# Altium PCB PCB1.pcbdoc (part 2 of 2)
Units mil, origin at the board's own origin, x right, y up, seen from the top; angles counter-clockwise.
Board outline 5175 x 2060 mil, 4 copper layers (Top Layer, Inner1, Inner2, Bottom Layer), stack 62.447 mil thick; 102 components, 59 nets, 316 pads, 177 vias.
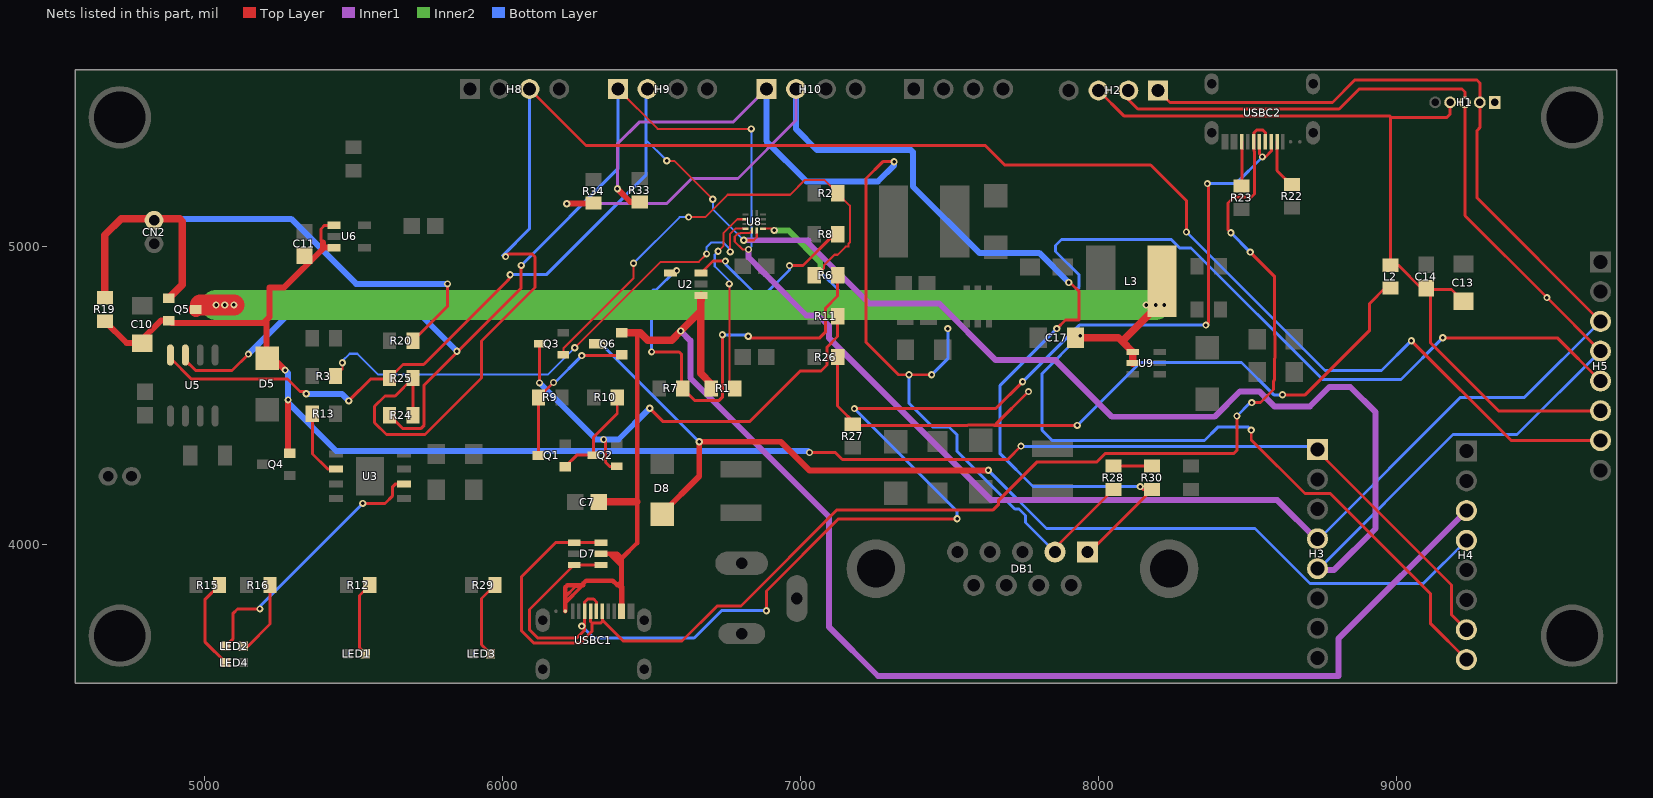
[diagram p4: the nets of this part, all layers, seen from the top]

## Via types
v1: diameter 24.02, hole 12, Top Layer to Bottom Layer, 177 vias

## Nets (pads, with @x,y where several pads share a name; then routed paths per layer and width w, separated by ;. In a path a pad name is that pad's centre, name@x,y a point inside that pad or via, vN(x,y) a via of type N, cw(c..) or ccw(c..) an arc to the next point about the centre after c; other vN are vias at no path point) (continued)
ID_INV: Q2.1 Q3.3 R11.2 | length 1618
  Top Layer w10: v1(6123.78,4543.56) 6123.78,4674.06 Q3.3@6124.73,4675 ; v1(6338.78,4353.57) 6345,4347.35 6345,4277.35 6358.78,4263.57 Q2.1@6383.47,4263.57 ; v1(6493.78,4458.57) 6538.78,4413.57 6828.78,4413.57 6998.78,4583.56 7068.78,4583.56 7088.78,4603.56 7088.78,4663.56 7124.37,4699.16 R11.2@7124.37,4767.5
  Bottom Layer w20: v1(6123.78,4543.56) 6313.78,4353.57 v1(6338.78,4353.57) 6388.78,4353.57 v1(6493.78,4458.57)
LED_CHG_A: LED4.1 R15.2 | length 309.2
  Top Layer w10: R15.2@5049.37,3865 5000.47,3816.1 5000.47,3675 LED4.1@5070.47,3605
LED_DONE_A: LED2.2 R16.2 | length 251.3
  Top Layer w10: LED2.2@5129.49,3660.01 5145,3660 5219.37,3734.37 R16.2@5219.37,3865
LED_EXT_A: LED1.2 R12.2 | length 252.7
  Top Layer w10: LED1.2@5539.56,3635 5519.56,3655 5519.56,3830.2 R12.2@5554.37,3865
LED_ON_A: LED3.2 R29.2 | length 261
  Top Layer w10: LED3.2@5959.49,3635.01 5929.49,3665 5929.49,3820.12 R29.2@5974.37,3865
PROG: R13.1 U3.2 | length 234.9
  Top Layer w10: R13.1@5360.63,4440 5361.88,4438.75 5361.88,4305 5411.88,4255 U3.2@5440.5,4255
PWR_SW_G: CN2.2 Q5.1 R19.2 R20.1 | length 2088.3
  Top Layer w10: R20.1@5699.37,4685 5815,4800.63 v1(5815,4876.01)
  Top Layer w25: R19.2@4665,4829.37 4665,5040 4720,5095 4829.37,5095 4830,5094.37 4915.63,5094.37 4925,5085 4925,4872.68 Q5.1@4879.73,4827.4
  Bottom Layer w20: CN2.2@4830,5094.37 5290,5094.37 5508.36,4876.01 v1(5815,4876.01)
Q2_G: Q1.1 Q2.3 R10.2 | length 337.7
  Top Layer w10: Q1.1@6210.27,4262.6 6248.65,4300.97 Q2.3@6304.73,4300.97 6304.72,4360.97 6384.72,4440.97 6384.72,4494.64 R10.2@6384.37,4495
RS485_A: DB1.1 H10.2 R30.1 R34.1 | length 4004.9
  Top Layer w10: v1(7860,4725.63) 7889.37,4755 7935,4755 7935,4850 7904.37,4880.63 v1(7900,4880.63) ; DB1.1@7963.11,3975.9 7970.28,3975.9 R30.1@8180,4185.63 8150,4185.63 v1(8140,4195.63)
  Top Layer w20: v1(6215,5145) 6302.66,5145 R34.1@6305.39,5147.73
  Inner1 w10: v1(6215,5145) 6550,5145 6635,5230 6790,5230 6985,5425 H10.2@6985,5530
  Bottom Layer w10: v1(7860,4725.63) 7670,4535.63 7670,4305.63 7780,4195.63 v1(8140,4195.63)
  Bottom Layer w20: H10.2@6985,5530 6985,5395 7055,5325 7370,5325 7377.07,5317.93 7377.07,5202.93 7600,4980 7800.63,4980 v1(7900,4880.63)
RS485_B: DB1.2 H10.1 R28.2 R33.1 | length 3753.1
  Top Layer w10: v1(7314.06,5285.9) 7275.9,5285.9 7220,5230 7220,4680 7329.1,4570.9 v1(7364.06,4570.9) v1(7440,4570.9) ; DB1.2@7854.05,3975.9 7854.06,3989.68 R28.2@8050,4185.63
  Top Layer w20: v1(6385,5195) 6429.37,5150.63 R33.1@6460,5150.63
  Inner1 w10: v1(6385,5195) 6385,5345 6460,5420 6775,5420 H10.1@6885,5530
  Bottom Layer w10: v1(7364.06,4570.9) 7364.06,4475.17 7443.39,4395.84 7497.99,4395.84 7525.54,4368.29 7525.54,4313.69 7719.24,4120 7733.38,4120 7755,4098.37 7755,4074.96 DB1.2@7854.05,3975.9 ; v1(7440,4570.9) 7494.06,4624.96 v1(7494.06,4725.9)
  Bottom Layer w20: H10.1@6885,5530 6885,5355 7020,5220 7260,5220 7314.06,5274.06 v1(7314.06,5285.9)
SCL: H1.3 H2.2 H3.5 H5.4 H9.2 R25.1 U5.4 U8.8 | length 9488.2
  Top Layer w7.09: v1(6550.63,5288.99) 6576.64,5288.99 v1(6705.45,5160.18) ; v1(6809.48,5022.35) 6842.98,5022.35 6852.87,5032.24 U8.8@6852.87,5055.47
  Top Layer w10: U5.4@4885,4637.37 4885,4626.93 4955,4556.93 5278.07,4556.93 5320,4515 5333,4515 v1(5341.07,4506.93) ; v1(5483.72,4483.35) 5557.29,4556.93 5617.56,4556.93 R25.1@5620.63,4560 5665.63,4605 5735,4605 6017,4887 6017,4887.73 6025.16,4895.89 v1(6025.16,4906.64) ; H2.2@8100,5525 8100,5495 8132,5463 8808,5463 8875,5530 9220,5530 9230,5520 H1.3@9230,5485 9230,5105 v1(9505,4830) H5.4@9685,4650
  Inner1 w20: v1(6809.48,5022.35) 7024.79,5022.35 7026.07,5021.07 ; 7020,5020 7230,4810 7465,4810 7655,4620 7855,4620 8045,4430 8390,4430 8475,4515 8540,4515 8590,4465 8710,4465 8775,4530 8845,4530 8930,4445 8930,4055 8790,3915 H3.5@8735,3915
  Bottom Layer w7.09: 6480.63,5360 6550.63,5290 v1(6550.63,5288.99) ; v1(6705.45,5160.18) 6705.45,5126.38 v1(6809.48,5022.35)
  Bottom Layer w10: v1(6025.16,4906.64) 6146.64,4906.64 6480.63,5240.63 6480.63,5360 6480.63,5523.96 H9.2@6486.67,5530 ; H3.5@8735,3915 9190,4370 9405,4370 H5.4@9685,4650
  Bottom Layer w20: v1(5341.07,4506.93) 5460.14,4506.93 v1(5483.72,4483.35)
SDA: H1.2 H2.1 H3.4 H5.3 H9.1 R24.1 U5.3 U8.7 | length 9385.5
  Top Layer w7.09: H9.1@6386.67,5530 6520.66,5396.01 v1(6834.73,5396.01) ; v1(6825.24,4991.39) 6805.46,4991.39 6779.25,5017.6 6779.25,5034.25 6790,5045 6797.41,5045 6799.31,5046.9 6829.78,5046.9 6835.96,5053.08 6835.96,5054.3 U8.7@6837.13,5055.47
  Top Layer w10: U5.3@4935,4637.37 4935,4620 4970,4585 5091.67,4585 v1(5146.67,4640) ; R24.1@5620.63,4435 5665.63,4390 5725,4390 5736.67,4401.67 5736.67,4536.67 6062.37,4862.37 v1(6062.37,4937.74) ; H2.1@8200,5525 8240,5485 8785,5485 8860,5560 9270,5560 9280,5550 H1.2@9280,5485 9280,5400 9270,5390 9270,5165 H5.3@9685,4750
  Inner1 w20: v1(6825.24,4991.39) 6825.24,4964.76 6878.17,4911.83 6878.58,4911.83 6882.99,4907.42 6883.17,4907.42 6900.74,4889.84 6900.74,4889.26 7020,4770 7060,4770 7095,4735 7095,4695 7640,4150 8600,4150 H3.4@8735,4015
  Bottom Layer w7.09: v1(6825.24,4991.39) 6834.73,5000.88 v1(6834.73,5396.01)
  Bottom Layer w10: v1(6062.37,4937.74) 6386.67,5262.03 H9.1@6386.67,5530 ; H3.4@8740.63,4015 8735,4015 9215,4495 9430,4495 H5.3@9685,4750
  Bottom Layer w20: v1(5146.67,4640) 5281.67,4775 5721.67,4775 v1(5846.67,4650)
SENS_PWR: C13.1 C14.2 H1.4 H2.3 H5.6 L2.2 | length 2871.9
  Top Layer w10: H2.3@8000,5525 8085,5440 8976.66,5440 8981.66,5435 ; C14.2@9100,4860.63 9084.37,4860.63 9006.96,4938.04 L2.2@8980,4938.04 8980,5433.34 8981.66,5435 ; H1.4@9180,5475 9180,5445 9170,5435 8981.66,5435 ; C13.1@9225,4817.3 9185,4857.3 9115,4857.3 9115,4677.3 9342.3,4450 H5.6@9685,4450
SENS_SEL: L2.1 R26.2 R27.2 | length 2536
  Top Layer w10: R26.2@7124.37,4630 7124.37,4465.72 7188.88,4401.21 7560.83,4401.21 cw(c7565.63,4390.21) 7565.63,4402.21 7644.37,4402.21 cw(c7644.37,4390.21) 7649.17,4401.21 7928.28,4401.21 v1(7928.64,4400.84) ; 7655,4404.37 v1(7765,4514.37) ; v1(8617.54,4503.71) 8693.71,4503.71 8910,4720 8910,4810 8961.96,4861.96 L2.1@8980,4861.96
  Bottom Layer w10: v1(7928.64,4400.84) 8139.76,4611.96 8480,4611.96 8588.26,4503.71 v1(8617.54,4503.71)
SINK_G: Q1.3 Q6.1 R9.1 | length 534.1
  Top Layer w10: Q1.3@6119.73,4300 6119.73,4494.09 R9.1@6120.63,4495 v1(6170.63,4545) ; v1(6265.63,4635) 6397.67,4635 Q6.1@6400.27,4637.6
  Bottom Layer w10: v1(6170.63,4545) 6175.63,4545 v1(6265.63,4635)
SRC_EN_N: R6.2 R7.2 U2.4 | length 1461
  Top Layer w10: v1(6500,4647.49) 6592.51,4647.49 6600,4640 6600,4529.37 R7.2@6604.37,4525 6644.37,4485 6727.21,4485 6737.44,4495.23 v1(6737.44,4705) ; v1(6824.37,4700) 6829.37,4695 7054.06,4694.94 ; 7054.13,4695 7064.37,4695 7084.37,4715 7084.37,4795 7124.37,4835 R6.2@7124.37,4905
  Bottom Layer w10: v1(6500,4647.49) 6500,4850.08 6504.92,4855 6515,4855 v1@6580,4920 ; v1(6737.44,4705) 6819.37,4705 v1(6824.37,4700)
  other v1: 6583.9,4920.27
STDBY_N: LED2.1 U3.6 | length 897.7
  Top Layer w10: LED2.1@5070.51,3659.99 5095.51,3685 5095.51,3770.51 5110,3785 v1(5185.51,3785) ; v1(5530.51,4139.03) 5604.91,4139.03 5630.88,4165 5630.88,4195 5640.88,4205 U3.6@5669.5,4205
  Bottom Layer w10: v1(5185.51,3785) 5185.51,3794.03 v1(5530.51,4139.03)
SYS: C10.2 C11.2 D5.1 H3.1 H4.7 Q4.2 Q5.2 R19.1 U6.1 U6.3 | length 5981.9
  Top Layer w10: 5397.07,5014.36 5390,5021.43 5390,5060 5402.39,5072.39 U6.1@5433.82,5072.39 ; v1(7030,4310.01) 7116.6,4310.01 7139.99,4286.61 7694.99,4286.61 v1(7739.99,4331.61) ; H3.1@8735,4315 9185,3865 9185,3765 H4.7@9235,3715
  Top Layer w20: R19.1@4665,4750.63 4738.33,4677.3 4777.3,4677.3 4852.6,4752.6 Q5.2@4879.73,4752.6 4887.96,4744.36 5197.07,4744.36 5207.07,4754.36 ; v1(5270,4586.61) 5230,4626.61 D5.1@5210,4626.61 5207.07,4629.54 5207.07,4754.36 ; v1(5280,4486.61) 5280,4312.68 Q4.2@5285.27,4307.4 ; 5397.07,5000.22 5399.68,4997.61 U6.3@5433.82,4997.61 ; 5397.07,5014.36 5397.07,4994.36 5267.07,4864.36 5217.07,4864.36 5217.07,4764.36 5207.07,4754.36
  Bottom Layer w10: v1(7739.99,4331.61) 7741.61,4330 8720,4330 H3.1@8735,4315
  Bottom Layer w20: v1(5270,4586.61) 5280,4576.61 v1(5280,4486.61) 5280,4476.61 5441.61,4315 7025,4315 v1(7030,4310.01)
SYS_SW: C17.1 H4.8 L3.1 Q5.3 U9.4 U9.5 | length 6011.1
  Top Layer w10: C17.1@7930.74,4695 v1(7938.21,4702.48) ; v1(8512.7,4385) 8512.7,4352.3 8693,4172 8778,4172 9115,3835 9115,3735 H4.8@9235,3615
  Top Layer w25: C17.1@7922.7,4695 8067.16,4695 8079.25,4682.91 ; U9.5@8114.76,4610 U9.4@8114.76,4647.4 8079.25,4682.91 ; L3.1@8196.49,4800.14 8079.25,4682.91 ; L3.1@8212.48,4816.14 L3.1@8212.48,4885
  Top Layer w50: Q5.3@4970.27,4790 Q5.3@4985.27,4805
  Top Layer w70: Q5.3@4985.27,4805 v1(5038.21,4805) v1(5067.37,4805) 5097.64,4805 v1(5098,4805.36)
  Inner2 w100: v1(5038.21,4805) v1(5067.37,4805) 6836.14,4805 6836.32,4804.81 6895.15,4804.81 6895.33,4805 v1(8160,4805) v1(8191.63,4805)
  Bottom Layer w10: v1(7938.21,4702.48) 7810,4574.26 7810,4385 7844.39,4350.61 8355.61,4350.61 8400,4395 8502.7,4395 v1(8512.7,4385)
  other v1: 8220,4805
TERM_B: R28.1 R30.2 | length 130
  Top Layer w10: R28.1@8050,4264.37 R30.2@8180,4264.37
TUSB_INT: R3.2 U8.6 | length 1735.5
  Top Layer w7.09: R3.2@5439.37,4566.67 5461.99,4589.29 v1(5461.99,4611.38) ; v1(6241.99,4661.38) 6530.61,4950 6658.28,4950 v1(6684.66,4976.38) ; v1(6763.77,4983.16) 6763.77,5043.77 6781.38,5061.38 U8.6@6815.47,5061.38
  Bottom Layer w7.09: v1(5461.99,4611.38) 5461.99,4616.99 5486.38,4641.38 5511.99,4641.38 5581.99,4571.38 6151.99,4571.38 v1(6241.99,4661.38) ; v1(6684.66,4976.38) 6684.66,4999.66 6700,5015 6740,5015 6763.77,4991.23 v1(6763.77,4983.16)
UPDI: H1.1
USB_DN: D7.3 D7.4 USBC1.A7 USBC1.B7 USBC2.A7 USBC2.B7 | length 4881.7
  Top Layer w10: v1(6265.47,3727.41) 6275.47,3737.41 ; USBC1.A7@6314.84,3777.41 6315.47,3778.03 6315.47,3808 6305.47,3818 6285.47,3818 6275.47,3808 USBC1.B7@6275.47,3777.41 6275.47,3737.41 ; D7.4@6330.24,3932.6 D7.3@6239.76,3932.6 6090,3782.84 6090,3715 6117.59,3687.41 6248.85,3687.41 6275.47,3714.02 6275.47,3737.41 ; v1(6885.47,3778.99) 6885.47,3845.47 7127.4,4087.4 v1(7525.47,4087.4) ; v1(7180.47,4457.4) 7655.47,4457.4 v1(7745.47,4547.4) ; v1(8360.46,4737.4) 8370,4746.94 8370,5207.87 v1(8365.46,5212.4) ; USBC2.A7@8540.16,5352.59 8540.16,5312.1 v1(8550.16,5302.1) 8560.16,5302.1 8580.16,5322.1 8580.16,5351.96 USBC2.B7@8579.53,5352.59
  Bottom Layer w10: v1(6265.47,3727.41) 6305.47,3687.41 6642.95,3687.41 6734.54,3778.99 v1(6885.47,3778.99) ; v1(7180.47,4457.4) 7525.47,4112.4 v1(7525.47,4087.4) ; v1(7745.47,4547.4) 7935.47,4737.4 v1(8360.46,4737.4) ; v1(8365.46,5212.4) 8460.46,5212.4 v1(8550.16,5302.1)
USB_DP: D7.1 D7.6 USBC1.A6 USBC1.B6 USBC2.A6 USBC2.B6 | length 4692.3
  Top Layer w10: USBC1.A6@6295.16,3777.41 6295.16,3742 6299.76,3737.4 ; D7.6@6330.24,4007.4 D7.1@6239.76,4007.4 6177.4,4007.4 6063.93,3893.93 6063.93,3711.23 6105.16,3670 6260,3670 6299.76,3709.76 6299.76,3737.4 ; USBC1.B6@6334.53,3777.41 6334.53,3747.41 ; v1(8444.53,5047.4) 8434.53,5057.4 8434.53,5147.4 8454.53,5167.4 8513.25,5167.4 8523.25,5177.4 8523.25,5321.03 8522.25,5322.03 8522.25,5383.16 8532.28,5393.19 8550.47,5393.19 8560.47,5383.19 8560.47,5353.22 USBC2.A6@8559.84,5352.59 ; v1(8464.53,4432.4) 8464.53,4317.4 8454.53,4307.4 8023.27,4307.4 7993.27,4277.4 7792.4,4277.4 7665,4150 7665,4135.86 7646.55,4117.4 7122.4,4117.4 6800,3795 6720,3795 6602.41,3677.41 6404.53,3677.41 6334.53,3747.41 ; v1(8509.53,4982.4) 8590,4901.93 8590,4706.1 8592.53,4703.57 8592.53,4626.43 8590,4623.9 8590,4552.88 8587.53,4550.41 8587.53,4521.43 8543.51,4477.4 v1(8514.53,4477.4) ; 6299.76,3737.4 6329.76,3737.4 6334.53,3742.17 6334.53,3747.41
  Bottom Layer w10: v1(8444.53,5047.4) v1(8509.53,4982.4) ; v1(8464.53,4432.4) 8509.53,4477.4 v1(8514.53,4477.4)
USB_ID: H5.5 Q3.1 R2.2 R6.1 U8.9 | length 5100.5
  Top Layer w6: U8.9@6874.53,5061.38 6905.9,5061.38 v1(6911.75,5055.53)
  Top Layer w7.09: Q3.1@6203.47,4637.6 6204.37,4638.51 6204.37,4660 6439.37,4895 v1(6439.37,4945) ; v1(6624.37,5100) 6680,5100 6755,5175 6965,5175 7015,5225 7079.37,5225 R2.2@7124.37,5180 7165.63,5138.74 7165.63,5015 7160.88,5010.25 7160.88,5000.88 7160.75,5000.75 7151.38,5000.75 7124.31,4973.68 7113.68,4973.68 7078.52,4938.52 7078.52,4927.89 R6.1@7055.63,4905
  Top Layer w10: R6.1@7045.63,4905 7055.63,4905 7055.63,4905.93 v1(7066.13,4916.43) ; v1(9155.62,4695) 9540,4695 H5.5@9685,4550
  Inner2 w20: v1(6911.75,5055.53) 6959.47,5055.53 7066.13,4948.87 v1(7066.13,4916.43)
  Bottom Layer w7.09: v1(6439.37,4945) 6594.37,5100 v1(6624.37,5100)
  Bottom Layer w10: v1(7066.13,4916.43) 7137.56,4845 7915,4845 7935,4865 7935,4905.63 7855.63,4985 7855.63,5005 7875.63,5025 8244.37,5025 8272.67,4996.7 8310.8,4996.7 8752.5,4555 9015.62,4555 v1(9155.62,4695)
USB_OC_N: R8.2 U2.3 | length 615.4
  Top Layer w10: U2.3@6666.19,4912.4 6706.18,4952.4 v1(6747.84,4952.4) ; v1(6962.84,4937.4) 7007.84,4937.4 7112.84,5042.4 R8.2@7124.27,5042.4
  Bottom Layer w10: v1(6747.84,4952.4) 6747.84,4942.16 6845,4845 6885,4845 6962.84,4922.84 v1(6962.84,4937.4)
VBUS_DET: R1.2 U8.4 | length 654.8
  Top Layer w7.09: v1(6723.32,4985.33) 6741.99,5003.99 6741.99,5046.99 6787.87,5092.87 U8.4@6815.47,5092.87 ; v1(6760.62,4876.01) 6761.99,4874.64 6761.99,4542.38 R1.2@6779.37,4525
  Bottom Layer w7.09: v1(6723.32,4985.33) 6711.99,4973.99 6711.99,4934.66 6760.62,4886.03 v1(6760.62,4876.01)
VBUS_EXT: C7.1 D7.5 H4.3 Q6.2 R1.1 U2.1 USBC1.A4B9 USBC1.B4A9 | length 6528
  Top Layer w10: 6210.51,3804.17 6266.34,3860 ; 6210.51,3807.41 6263.1,3860 ; 6210.51,3825.51 6245,3860 6263.1,3860 ; 6271.34,3865 6266.34,3860 ; 6356.34,3970 6396.34,3930 ; 6366.34,3970 6367.92,3968.42 ; 6370.24,3970 6400,3940.24 6400.24,3940 ; 6384.5,3865 6389.5,3860 ; 6399.5,3860.5 6399.5,3850.74 ; 6399.5,3940 6367.92,3968.42 ; 6400.24,3850 6399.5,3850.74 ; 6263.1,3860 6266.34,3860 ; 6367.92,3968.42 6396.34,3940 6396.34,3930 ; 6389.5,3860 6390.24,3860 6396.34,3853.9 ; 6389.5,3860 6396.34,3853.16 ; 6396.34,3853.16 6396.34,3853.9 ; 6396.34,3853.16 6396.34,3850 6396.34,3780.56 USBC1.B4A9@6399.49,3777.41 6399.5,3850 ; 6396.34,3853.16 6397.92,3851.58 6399.5,3850 ; 6396.34,3853.9 6399.5,3850.74 ; 6396.34,3853.9 6396.34,3863.66 6396.34,3930 ; 6399.5,3850 6399.5,3850.74
  Top Layer w15: USBC1.A4B9@6210.51,3777.4 6210.51,3804.17 6210.51,3807.41 6210.51,3825.51 6210.51,3857.93 6217.58,3865 6271.34,3865 6271.34,3871.34 6280,3880 6370,3880 6384.75,3865.25 ; D7.5@6330.24,3970 6330.85,3970.61 6384.39,3970.61 6400,3955 ; 6384.5,3865 6384.75,3865.25 ; USBC1.B4A9@6399.49,3777.41 6402.07,3779.98 6402.07,3860 6400,3860 ; 6451.09,4712.4 6451.09,4144.37 6451.09,4006.09 6400,3955 ; 6384.75,3865.25 6389.5,3870 6390,3870 6396.34,3863.66 6399.5,3860.5 6400,3860 ; 6400,3860 6400,3940.24 6400,3955
  Top Layer w25: C7.1@6324.37,4140 6328.74,4144.37 6451.09,4144.37 ; Q6.2@6400.27,4712.4 6451.09,4712.4 6461.97,4712.4 6486.97,4687.4 6567.4,4687.4 v1(6597.68,4717.68) 6665,4785 ; R1.1@6700.63,4540 6665,4575.63 6665,4785 ; 6665,4785 6665,4820 ; 6665,4820 6665,4836.41 U2.1@6666.19,4837.6 6666.19,4821.19 6665,4820
  Inner1 w20: v1(6597.68,4717.68) 6630,4685.37 6630,4560 7095,4095 7095,3725 7260,3560 8805,3560 8805,3685 H4.3@9235,4115
  Bottom Layer w10: H4.3@9225,4095 H4.3@9235,4105
VBUS_SINK: D8.2 H4.4 Q6.3 | length 3613.2
  Top Layer w10: Q6.3@6309.73,4675 6315,4669.72 v1(6335,4669.72)
  Top Layer w20: D8.2@6535,4103.39 6535,4104.99 6660,4230 v1(6660,4346.01) 6933.99,4346.01 7029.7,4250.3 v1(7630.31,4250.3)
  Bottom Layer w10: v1(6335,4669.72) 6658.72,4346.01 v1(6660,4346.01) ; v1(7630.31,4250.3) 7825.61,4055 8525,4055 8710,3870 9090,3870 H4.4@9235,4015
WS_CC1: R22.2 USBC2.A5 | length 168.5
  Top Layer w10: USBC2.A5@8599.21,5352.59 8599.21,5255.95 R22.2@8650,5205.15
WS_CC2: R23.2 USBC2.B5 | length 147.9
  Top Layer w10: R23.2@8480,5205.15 8481.1,5206.25 USBC2.B5@8481.1,5352.59
WS_VOUT: H5.7 H8.3 R24.2 R25.2 | length 6226.8
  Top Layer w10: R24.2@5699.37,4435 R25.2@5699.37,4560 5639.37,4500 5605,4500 5570,4465 5570,4410 5610,4370 5739.71,4370 5929.37,4559.66 5929.37,4684.37 6108.47,4863.47 6108.47,4966.65 6098.47,4976.65 6019.26,4976.65 v1(6010.15,4967.53) ; H8.3@6090,5530 6280,5340 7620,5340 7685,5275 8175,5275 8295,5155 v1(8295,5050) ; v1(9049.99,4685) 9384.99,4350 H5.7@9685,4350
  Bottom Layer w10: v1(6010.15,4967.53) 6007.05,4970.63 6000,4970.63 6090,5060.63 H8.3@6090,5530 ; v1(8295,5050) 8760,4585 8949.99,4585 v1(9049.99,4685)
pads on no net: DB1.3 DC1.3 H8.1 U6.4 U8.3 U9.6 USBC1.A8 USBC1.B8 USBC2.A8 USBC2.B8

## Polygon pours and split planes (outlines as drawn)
GND on Top Layer (solid, remove dead copper, pour order 0): 4530,5740 4530,3480 9815,3480 9815,5740
GND on Bottom Layer (solid, remove dead copper, pour order 4): 4505,5655 4505,3390 9835,3390 9835,5655
5V_IN on Inner1 (solid, remove dead copper): 4505,5660 4505,3475 9815,3475 9815,5660
GND on Inner2 (solid, remove dead copper): 4490,5655 4490,3400 10080,3400 10080,5655

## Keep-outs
Board Outline Layer:
  region: 4927.5,5320 ccw(c4927.5,5270) 4877.5,5270 ccw(c4927.5,5270) 4927.5,5220 5182.5,5220 ccw(c5182.5,5270) 5232.5,5270 ccw(c5182.5,5270) 5182.5,5320
  region: 4927.5,5320 ccw(c4927.5,5270) 4877.5,5270 ccw(c4927.5,5270) 4927.5,5220 5182.5,5220 ccw(c5182.5,5270) 5232.5,5270 ccw(c5182.5,5270) 5182.5,5320
  region: 5712.5,5320 ccw(c5712.5,5270) 5662.5,5270 ccw(c5712.5,5270) 5712.5,5220 5967.5,5220 ccw(c5967.5,5270) 6017.5,5270 ccw(c5967.5,5270) 5967.5,5320
  region: 5712.5,5320 ccw(c5712.5,5270) 5662.5,5270 ccw(c5712.5,5270) 5712.5,5220 5967.5,5220 ccw(c5967.5,5270) 6017.5,5270 ccw(c5967.5,5270) 5967.5,5320
  region: 4927.5,4070 ccw(c4927.5,4020) 4877.5,4020 ccw(c4927.5,4020) 4927.5,3970 5182.5,3970 ccw(c5182.5,4020) 5232.5,4020 ccw(c5182.5,4020) 5182.5,4070
  region: 4927.5,4070 ccw(c4927.5,4020) 4877.5,4020 ccw(c4927.5,4020) 4927.5,3970 5182.5,3970 ccw(c5182.5,4020) 5232.5,4020 ccw(c5182.5,4020) 5182.5,4070
  region: 5712.5,4070 ccw(c5712.5,4020) 5662.5,4020 ccw(c5712.5,4020) 5712.5,3970 5967.5,3970 ccw(c5967.5,4020) 6017.5,4020 ccw(c5967.5,4020) 5967.5,4070
  region: 5712.5,4070 ccw(c5712.5,4020) 5662.5,4020 ccw(c5712.5,4020) 5712.5,3970 5967.5,3970 ccw(c5967.5,4020) 6017.5,4020 ccw(c5967.5,4020) 5967.5,4070
  region: 5070,3740 cw(c5045,3740) 5020,3740 cw(c5045,3740)
  circle w0.1: c5045,3740 r25
  region: 5070,3740 5069.62,3735.66 5068.49,3731.45 5066.65,3727.5 5064.15,3723.93 5061.07,3720.85 5057.5,3718.35 5053.55,3716.51 5049.34,3715.38 5045,3715 5040.66,3715.38 5036.45,3716.51 5032.5,3718.35 5028.93,3720.85 5025.85,3723.93 5023.35,3727.5 5021.51,3731.45 5020.38,3735.66 5020,3740 5020.38,3744.34 5021.51,3748.55 5023.35,3752.5 5025.85,3756.07 5028.93,3759.15 5032.5,3761.65 5036.45,3763.49 5040.66,3764.62 5045,3765 5049.34,3764.62 5053.55,3763.49 5057.5,3761.65 5061.07,3759.15 5064.15,3756.07 5066.65,3752.5 5068.49,3748.55 5069.62,3744.34
  region: 5170,3740 cw(c5145,3740) 5120,3740 cw(c5145,3740)
  circle w0.1: c5145,3740 r25
  region: 5170,3740 5169.62,3735.66 5168.49,3731.45 5166.65,3727.5 5164.15,3723.93 5161.07,3720.85 5157.5,3718.35 5153.55,3716.51 5149.34,3715.38 5145,3715 5140.66,3715.38 5136.45,3716.51 5132.5,3718.35 5128.93,3720.85 5125.85,3723.93 5123.35,3727.5 5121.51,3731.45 5120.38,3735.66 5120,3740 5120.38,3744.34 5121.51,3748.55 5123.35,3752.5 5125.85,3756.07 5128.93,3759.15 5132.5,3761.65 5136.45,3763.49 5140.66,3764.62 5145,3765 5149.34,3764.62 5153.55,3763.49 5157.5,3761.65 5161.07,3759.15 5164.15,3756.07 5166.65,3752.5 5168.49,3748.55 5169.62,3744.34
  region: 5488,3741.25 cw(c5463,3741.25) 5438,3741.25 cw(c5463,3741.25)
  circle w0.1: c5463,3741.25 r25
  region: 5488,3741.25 5487.62,3736.91 5486.49,3732.7 5484.65,3728.75 5482.15,3725.18 5479.07,3722.1 5475.5,3719.6 5471.55,3717.76 5467.34,3716.63 5463,3716.25 5458.66,3716.63 5454.45,3717.76 5450.5,3719.6 5446.93,3722.1 5443.85,3725.18 5441.35,3728.75 5439.51,3732.7 5438.38,3736.91 5438,3741.25 5438.38,3745.59 5439.51,3749.8 5441.35,3753.75 5443.85,3757.32 5446.93,3760.4 5450.5,3762.9 5454.45,3764.74 5458.66,3765.87 5463,3766.25 5467.34,3765.87 5471.55,3764.74 5475.5,3762.9 5479.07,3760.4 5482.15,3757.32 5484.65,3753.75 5486.49,3749.8 5487.62,3745.59
  region: 5588,3741.25 cw(c5563,3741.25) 5538,3741.25 cw(c5563,3741.25)
  circle w0.1: c5563,3741.25 r25
  region: 5588,3741.25 5587.62,3736.91 5586.49,3732.7 5584.65,3728.75 5582.15,3725.18 5579.07,3722.1 5575.5,3719.6 5571.55,3717.76 5567.34,3716.63 5563,3716.25 5558.66,3716.63 5554.45,3717.76 5550.5,3719.6 5546.93,3722.1 5543.85,3725.18 5541.35,3728.75 5539.51,3732.7 5538.38,3736.91 5538,3741.25 5538.38,3745.59 5539.51,3749.8 5541.35,3753.75 5543.85,3757.32 5546.93,3760.4 5550.5,3762.9 5554.45,3764.74 5558.66,3765.87 5563,3766.25 5567.34,3765.87 5571.55,3764.74 5575.5,3762.9 5579.07,3760.4 5582.15,3757.32 5584.65,3753.75 5586.49,3749.8 5587.62,3745.59
  region: 5904,3742.25 cw(c5879,3742.25) 5854,3742.25 cw(c5879,3742.25)
  circle w0.1: c5879,3742.25 r25
  region: 5904,3742.25 5903.62,3737.91 5902.49,3733.7 5900.65,3729.75 5898.15,3726.18 5895.07,3723.1 5891.5,3720.6 5887.55,3718.76 5883.34,3717.63 5879,3717.25 5874.66,3717.63 5870.45,3718.76 5866.5,3720.6 5862.93,3723.1 5859.85,3726.18 5857.35,3729.75 5855.51,3733.7 5854.38,3737.91 5854,3742.25 5854.38,3746.59 5855.51,3750.8 5857.35,3754.75 5859.85,3758.32 5862.93,3761.4 5866.5,3763.9 5870.45,3765.74 5874.66,3766.87 5879,3767.25 5883.34,3766.87 5887.55,3765.74 5891.5,3763.9 5895.07,3761.4 5898.15,3758.32 5900.65,3754.75 5902.49,3750.8 5903.62,3746.59
  region: 6004,3742.3 cw(c5979,3742.3) 5954,3742.3 cw(c5979,3742.3)
  circle w0.1: c5979,3742.3 r25
  region: 6004,3742.3 6003.62,3737.96 6002.49,3733.75 6000.65,3729.8 5998.15,3726.23 5995.07,3723.15 5991.5,3720.65 5987.55,3718.81 5983.34,3717.68 5979,3717.3 5974.66,3717.68 5970.45,3718.81 5966.5,3720.65 5962.93,3723.15 5959.85,3726.23 5957.35,3729.8 5955.51,3733.75 5954.38,3737.96 5954,3742.3 5954.38,3746.64 5955.51,3750.85 5957.35,3754.8 5959.85,3758.37 5962.93,3761.45 5966.5,3763.95 5970.45,3765.79 5974.66,3766.92 5979,3767.3 5983.34,3766.92 5987.55,3765.79 5991.5,3763.95 5995.07,3761.45 5998.15,3758.37 6000.65,3754.8 6002.49,3750.85 6003.62,3746.64
  lines w0.1: 4877.5,4020 cw(c4927.5,4020) 4927.5,4070 5182.5,4070 cw(c5182.5,4020) 5232.5,4020 cw(c5182.5,4020) 5182.5,3970 4927.5,3970 cw(c4927.5,4020) 4877.5,4020 ; 4877.5,5270 cw(c4927.5,5270) 4927.5,5320 5182.5,5320 cw(c5182.5,5270) 5232.5,5270 cw(c5182.5,5270) 5182.5,5220 4927.5,5220 cw(c4927.5,5270) 4877.5,5270 ; 5662.5,4020 cw(c5712.5,4020) 5712.5,4070 5967.5,4070 cw(c5967.5,4020) 6017.5,4020 cw(c5967.5,4020) 5967.5,3970 5712.5,3970 cw(c5712.5,4020) 5662.5,4020 ; 5662.5,5270 cw(c5712.5,5270) 5712.5,5320 5967.5,5320 cw(c5967.5,5270) 6017.5,5270 cw(c5967.5,5270) 5967.5,5220 5712.5,5220 cw(c5712.5,5270) 5662.5,5270
  lines w5: 4565,3535 4565,5595 9740,5595 9740,3535 4565,3535

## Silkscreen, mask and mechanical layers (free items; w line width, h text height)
Top Silkscreen Layer:
  lines w5: 5010,3564 5010,3704 5188,3704 5188,3564 5010,3564 ; 5425,3565.25 5425,3705.25 5603,3705.25 5603,3565.25 5425,3565.25 ; 5840,3566.25 5840,3706.25 6018,3706.25 6018,3566.25 5840,3566.25
  text "NC" at 5920,5389.9 h60 r90
  text "SCL" at 6516.67,5354.6 h60 r90
  text "GND" at 6016.2,5351.3 h60 r90
  text "GND" at 6220,5351.3 h60 r90
  text "GND" at 7515.47,5351.3 h60 r90
  text "SDA" at 6415,5349.7 h60 r90
  text "SCL" at 8125,5348 h60 r90
  text "SCL" at 9335,5348.1 h45 r90
  text "GND" at 7922.5,5344.7 h60 r90
  text "GND" at 9235,5345 h45 r90
  text "SDA" at 9385,5345 h45 r90
  text "On the Waveshare: battery / switch OFF, battery socket / empty, and both the RS-485 / and CAN termination switches OFF." at 4840,5340 h60
  text "UPDI" at 9445,5335 h45 r90
  text "UPDI" at 8227.5,5330.5 h60 r90
  text "CANL" at 6618.33,5312.8 h60 r90
  text "CANH" at 6720,5309.5 h60 r90
  text "DB_DI1" at 7715,5268.1 h60 r90
  text "DB_DI0" at 7609.53,5253.4 h60 r90
  text "DB_DO1" at 7215,5247.1 h60 r90
  text "RS485B" at 6910,5240.5 h60 r90
  text "RS485A" at 7007.87,5237.3 h60 r90
  text "CHG_EN" at 7105.73,5234.1 h60 r90
  text "DB_COM" at 7410,5222.6 h60 r90
  text "SNS_PWR" at 9285,5220 h45 r90
  text "OUT TO / SENSOR" at 8050,5180 h60
  text "WS_VOUT" at 6112.4,5175.9 h60 r90
  text "SNS_PWR" at 8026.43,5175.7 h60 r90
  text "OUT TO / SENSOR" at 9200,5085 h60
  text "PWR_SW_G" at 4955,5055 h60
  text "GND" at 4955,4980 h60
  text "SWITCH" at 4745,4950 h60 r90
  text "5V_OUT" at 9375,4920 h60
  text "3V3_AON" at 9333.2,4816.96 h60
  text "SDA" at 9500.5,4713.91 h60
  text "SCL" at 9505.4,4622.27 h60
  text "USB_ID" at 9381.4,4530.63 h60
  text "SENS_PWR" at 9296.2,4421.09 h60
  text "WS_VOUT" at 9326.7,4318.04 h60
  text "SYS" at 8550.3,4290 h60
  text "12V_IN" at 8963,4285 h60
  text "CHG_EN" at 9379.9,4215 h60
  text "5V_OUT" at 8424.8,4195.8 h60
  text "5V_DC" at 8964.1,4182.66 h60
  text "3V3_AON" at 8383,4090.2 h60
  text "VBUS_EXT" at 8850,4080.31 h60
  text "GND" at 4795,4040 h60 r90
  text "SDA" at 8550.3,3984.6 h60
  text "VBUS_SINK" at 8832.5,3977.97 h60
  text "BATT +" at 4705,3920 h60 r90
  text "SCL" at 8555.2,3890.4 h60
  text "5V_IN" at 8986.9,3875.63 h60
  text "CAN_H" at 8465,3796.2 h60
  text "GREEN" at 5870,3780 h45
  text "YELLOW" at 5430,3775 h45
  text "BAT_NODE" at 8846.8,3773.29 h60
  text "CAN_L" at 8468.3,3690.6 h60
  text "SYS" at 9047.8,3670.94 h60
  text "GREEN" at 5195,3640 h45
  text "GND" at 8551.9,3585 h60
  text "SYS_SW" at 8915.8,3580 h60
  text "RED" at 5200,3575 h45
Bottom Silkscreen Layer:
  drawing of 14 lines, arcs and shapes, not listed
  text "NC" at 5852.5,5391.5 h60 r270
  text "GND" at 9105,5365 h45 r270
  text "SCL" at 9205,5365 h45 r270
  text "SDA" at 9255,5360 h45 r270
  text "SCL" at 6449.17,5356.2 h60 r270
  text "GND" at 7870,5355 h60 r270
  text "SCL" at 8075,5355 h60 r270
  text "GND" at 5948.7,5352.9 h60 r270
  text "GND" at 6152.5,5352.9 h60 r270
  text "GND" at 7452.97,5352.9 h60 r270
  text "SDA" at 6347.5,5351.3 h60 r270
  text "SDA" at 8175,5350 h60 r270
  text "UPDI" at 9310,5350 h45 r270
  text "CANL" at 6550.83,5314.4 h60 r270
  text "CANH" at 6652.5,5311.1 h60 r270
  text "DB_DI1" at 7652.5,5269.7 h60 r270
  text "DB_DI0" at 7547.03,5255 h60 r270
  text "DB_DO1" at 7157.5,5253.7 h60 r270
  text "RS485B" at 6852.5,5247.1 h60 r270
  text "RS485A" at 6950.37,5243.9 h60 r270
  text "CHG_EN" at 7048.23,5240.7 h60 r270
  text "SNS_PWR" at 9155,5235 h45 r270
  text "DB_COM" at 7347.5,5224.2 h60 r270
  text "SNS_PWR" at 7975,5180 h60 r270
  text "WS_VOUT" at 6044.9,5177.5 h60 r270
  text "PWR_SW_G" at 5210,5055 h60
  text "GND" at 4980,4980 h60
  text "5V_OUT" at 9606.45,4922.5 h60
  text "On the Waveshare: battery / switch OFF, battery socket / empty, and both the RS-485 / and CAN termination switches OFF." at 6390,4880 h60
  text "3V3_AON" at 9606.45,4819.46 h60
  text "SDA" at 9606.45,4716.41 h60
  text "SCL" at 9606.45,4624.77 h60
  text "USB_ID" at 9606.45,4533.13 h60
  text "SENS_PWR" at 9606.45,4423.59 h60
  text "WS_VOUT" at 9606.45,4320.54 h60
  text "SYS" at 8657.95,4292.5 h60
  text "12V_IN" at 9161.25,4282.5 h60
  text "BATTERY +" at 4645,4280 h60 r270
  text "GND" at 4720,4280 h60 r270
  text "CHG_EN" at 9606.45,4217.5 h60
  text "5V_OUT" at 8657.95,4198.3 h60
  text "5V_DC" at 9161.25,4180.16 h60
  text "U4" at 4765,4120 h45
  text "3V3_AON" at 8657.95,4092.7 h60
  text "VBUS_EXT" at 9161.25,4077.81 h60
  text "RS485 A" at 7930,4034.1 h60 r270
  text "DB_D01" at 7605,4030.2 h60 r270
  text "RS485 B" at 7820,4030 h60 r270
  text "10/30/2026 / BEN KASPER / REV 1 / PPM METER BOARD PCB FILES - 26" at 7185,4025 h60
  text "GND" at 7495,4025 h60 r270
  text "SDA" at 8657.95,3987.1 h60
  text "VBUS_SINK" at 9161.25,3975.47 h60
  text "SCL" at 8657.95,3892.9 h60
  text "5V_IN" at 9161.25,3873.13 h60
  text "DC JACK 12V" at 6890,3835 h60
  text "DB_COM" at 7720,3812.8 h60 r90
  text "DB_DI1" at 7825,3812.8 h60 r90
  text "DB_DI0" at 7940,3812.8 h60 r90
  text "DB9_12V" at 7610,3807.8 h60 r90
  text "CAN_H" at 8657.95,3798.7 h60
  text "BAT_NODE" at 9161.25,3770.79 h60
  text "CAN_L" at 8657.95,3693.1 h60
  text "SYS" at 9161.25,3668.44 h60
  text "GND" at 6844.8,3600 h60
  text "GND" at 8657.95,3587.5 h60
  text "SYS_SW" at 9161.25,3577.5 h60
Mechanical Layer:
  circle w0.1: c5045,3740 r25
  circle w0.1: c5145,3740 r25
  circle w0.1: c5463,3741.25 r25
  circle w0.1: c5563,3741.25 r25
  circle w0.1: c5879,3742.25 r25
  circle w0.1: c5979,3742.3 r25
  lines w0.1: 4877.5,4020 cw(c4927.5,4020) 4927.5,4070 5182.5,4070 cw(c5182.5,4020) 5232.5,4020 cw(c5182.5,4020) 5182.5,3970 4927.5,3970 cw(c4927.5,4020) 4877.5,4020 ; 4877.5,5270 cw(c4927.5,5270) 4927.5,5320 5182.5,5320 cw(c5182.5,5270) 5232.5,5270 cw(c5182.5,5270) 5182.5,5220 4927.5,5220 cw(c4927.5,5270) 4877.5,5270 ; 5662.5,4020 cw(c5712.5,4020) 5712.5,4070 5967.5,4070 cw(c5967.5,4020) 6017.5,4020 cw(c5967.5,4020) 5967.5,3970 5712.5,3970 cw(c5712.5,4020) 5662.5,4020 ; 5662.5,5270 cw(c5712.5,5270) 5712.5,5320 5967.5,5320 cw(c5967.5,5270) 6017.5,5270 cw(c5967.5,5270) 5967.5,5220 5712.5,5220 cw(c5712.5,5270) 5662.5,5270
Document Layer:
  lines w10: 5000,3535 5185,3535 ; 5002.5,3435 5187.5,3435 ; 5423.12,3536.25 5608.12,3536.25 ; 5425.62,3436.25 5610.62,3436.25 ; 5846.25,3537.25 6031.25,3537.25 ; 5848.75,3437.25 6033.75,3437.25

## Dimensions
4565,5835 to 9730,5835 on Document Layer
4240,5595 to 4240,3535 on Document Layer
4405,5270 to 4405,4020 on Document Layer
5265,3704 to 5265,3740 on Document Layer
5675,3704 to 5675,3564 on Document Layer
4860,3740 to 4860,3634 on Document Layer
4660,3740 to 4660,3535 on Document Layer
4425,3740 to 4425,3435 on Document Layer
5010,3220 to 5425,3220 on Document Layer
5603,3215 to 6018,3215 on Document Layer
5010,3000 to 5188,3000 on Document Layer
4715,5680 to 4565,5680 on Document Layer
9590,5710 to 9740,5710 on Document Layer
